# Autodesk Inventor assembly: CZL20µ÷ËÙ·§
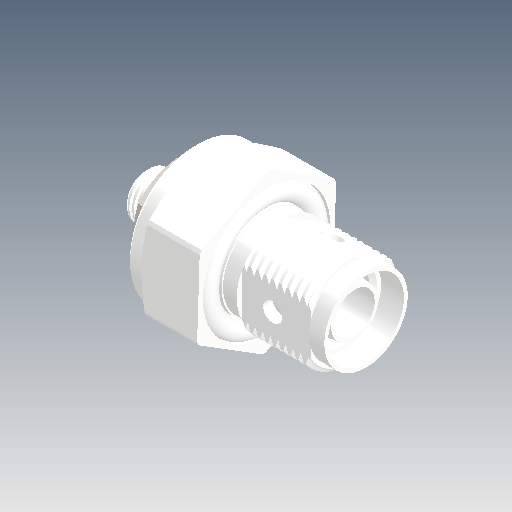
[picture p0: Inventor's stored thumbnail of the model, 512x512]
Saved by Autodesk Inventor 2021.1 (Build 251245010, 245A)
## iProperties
Created: 2021-05
Part Number: CZL20µ÷ËÙ·§
Document SubType Name: Assembly
Designer: user
Author: user
Revision Number: ÈÎºÎ
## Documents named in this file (4)
- D:\Vault_2016\Projekty\Clamptek\Hydraulic\CHLC\CHLC-40\Inventor\CHLC-FAMT40R\CZL20µ÷ËÙ·§.iam
- D:\Vault_2016\Projekty\Clamptek\Hydraulic\CHLC\CHLC-40\Inventor\CHLC-FAMT40R\20·§Ìå.ipt
- D:\Vault_2016\Projekty\Clamptek\Hydraulic\CHLC\CHLC-40\Inventor\CHLC-FAMT40R\20µ÷ËÙ¸Ë.ipt
- D:\Vault_2016\Projekty\Clamptek\Hydraulic\CHLC\CHLC-40\Inventor\CHLC-FAMT40R\hex thin nuts-grades ab-chamfered gb(GB_FASTENER_NUT_STNAB M6-S).ipt
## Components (3 placed, 3 different names)
1. 20·§Ìå_20
2. 20µ÷ËÙ¸Ë_21
3. hex thin nuts-grades ab-chamfered gb(GB_FASTENER_NUT_STNAB M6-S)_22
